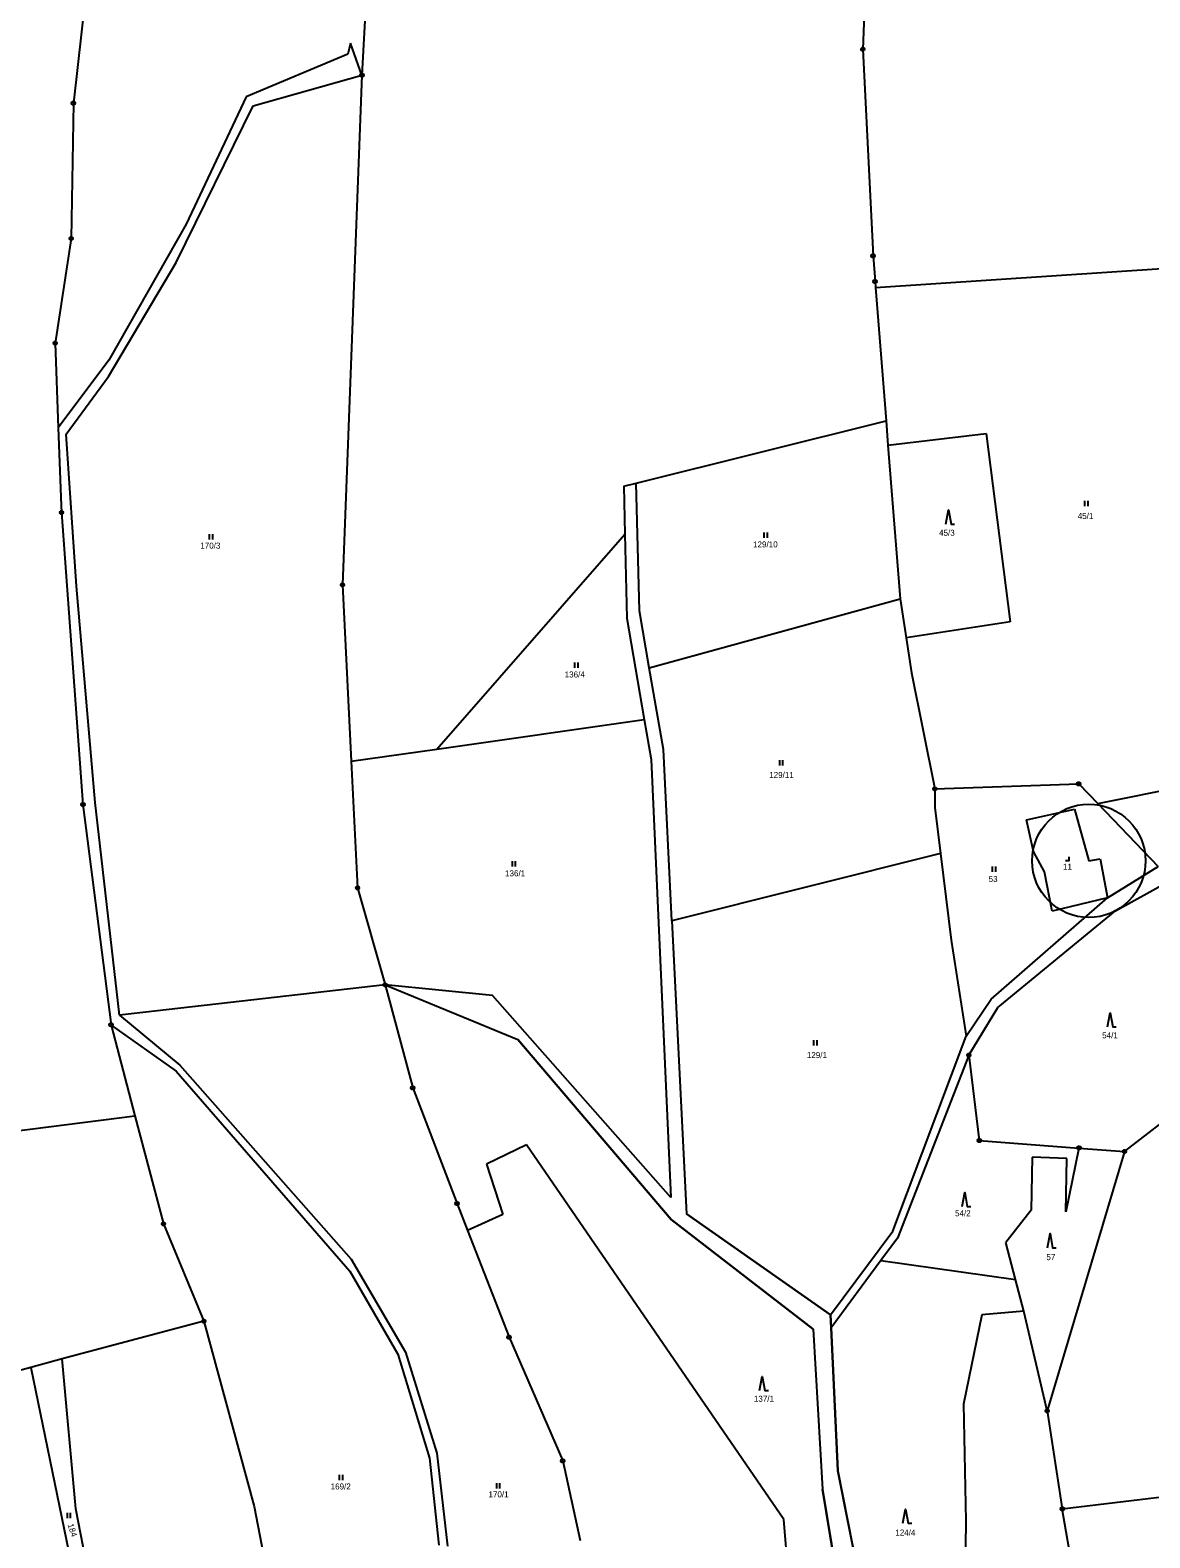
# Model space of a CAD drawing. Extents: x -580551 to -575069, y -1073031 to -1067931.
# Drawn here: x -576954.8 to -576638.6, y -1069440.4 to -1069014.5 of the extents above; entities that cross this region are included whole.
import ezdxf

# ---------------------------------------------------------------- set-up
doc = ezdxf.new("R2010")
doc.units = 0
for name, color, linetype in [('Druh pozemku', 7, 'Continuous'), ('Geodetické body', 7, 'Continuous'), ('Hranice z DKM', 7, 'Continuous'), ('Parcela', 7, 'Continuous'), ('Parcelní číslo', 7, 'Continuous'), ('Parcelní číslo_stavba', 7, 'Continuous'), ('stavební parcely', 7, 'Continuous'), ('Vrstva 6', 7, 'Continuous')]:
    doc.layers.add(name, color=color, linetype=linetype)

msp = doc.modelspace()

# ---------------------------------------------------------------- linework, layer by layer
at = {"layer": 'Druh pozemku'}
for p, q in [((-576657.09, -1069147.52), (-576657.09, -1069149.02)), ((-576656.09, -1069149.02), (-576656.09, -1069147.52)), ((-576904.29, -1069156.88), (-576904.29, -1069158.38)), ((-576903.29, -1069158.38), (-576903.29, -1069156.88)), ((-576747.6, -1069156.45), (-576747.6, -1069157.95)), ((-576746.6, -1069157.95), (-576746.6, -1069156.45)), ((-576801.1, -1069193.21), (-576801.1, -1069194.71)), ((-576800.1, -1069194.71), (-576800.1, -1069193.21)), ((-576743.26, -1069220.78), (-576743.26, -1069222.28)), ((-576742.26, -1069222.28), (-576742.26, -1069220.78)), ((-576818.75, -1069249.32), (-576818.75, -1069250.82)), ((-576817.75, -1069250.82), (-576817.75, -1069249.32)), ((-576683.16, -1069250.75), (-576683.16, -1069252.25)), ((-576682.16, -1069252.25), (-576682.16, -1069250.75)), ((-576733.62, -1069299.84), (-576733.62, -1069301.34)), ((-576732.62, -1069301.34), (-576732.62, -1069299.84)), ((-576867.56, -1069422.63), (-576867.56, -1069424.13)), ((-576866.56, -1069424.13), (-576866.56, -1069422.63)), ((-576823.15, -1069424.94), (-576823.15, -1069426.44)), ((-576822.15, -1069426.44), (-576822.15, -1069424.94)), ((-576944.4, -1069433.34), (-576944.4, -1069434.84)), ((-576943.4, -1069434.84), (-576943.4, -1069433.34))]:
    msp.add_line(p, q, dxfattribs=at)
for points in [[(-576696.28, -1069154.06), (-576695.53, -1069150.06), (-576694.78, -1069154.06), (-576693.78, -1069154.06)], [(-576662.44, -1069249.1), (-576661.44, -1069249.1), (-576661.44, -1069248.1)], [(-576650.61, -1069296.09), (-576649.86, -1069292.09), (-576649.11, -1069296.09), (-576648.11, -1069296.09)], [(-576691.67, -1069346.84), (-576690.92, -1069342.84), (-576690.17, -1069346.84), (-576689.17, -1069346.84)], [(-576667.57, -1069358.5), (-576666.82, -1069354.5), (-576666.07, -1069358.5), (-576665.07, -1069358.5)], [(-576748.82, -1069398.84), (-576748.07, -1069394.84), (-576747.32, -1069398.84), (-576746.32, -1069398.84)], [(-576708.35, -1069436.32), (-576707.6, -1069432.32), (-576706.85, -1069436.32), (-576705.85, -1069436.32)]]:
    msp.add_lwpolyline(points, dxfattribs=at)
at = {"layer": 'Geodetické body'}
for p, q in [((-576719.81, -1069019.97), (-576719.57, -1069019.97)), ((-576861.26, -1069027.25), (-576861.02, -1069027.25)), ((-576942.75, -1069035.14), (-576942.51, -1069035.14)), ((-576943.37, -1069073.41), (-576943.13, -1069073.41)), ((-576716.91, -1069078.31), (-576716.67, -1069078.31)), ((-576716.34, -1069085.54), (-576716.1, -1069085.54)), ((-576947.89, -1069102.98), (-576947.65, -1069102.98)), ((-576946.11, -1069150.82), (-576945.87, -1069150.82)), ((-576866.73, -1069171.24), (-576866.49, -1069171.24)), ((-576699.47, -1069228.86), (-576699.23, -1069228.86)), ((-576658.82, -1069227.41), (-576658.58, -1069227.41)), ((-576940.05, -1069233.25), (-576939.81, -1069233.25)), ((-576862.52, -1069256.8), (-576862.28, -1069256.8)), ((-576854.68, -1069284.2), (-576854.44, -1069284.2)), ((-576932.12, -1069295.57), (-576931.88, -1069295.57)), ((-576689.87, -1069304.12), (-576689.63, -1069304.12)), ((-576846.9, -1069313.32), (-576846.66, -1069313.32)), ((-576686.91, -1069328.19), (-576686.67, -1069328.19)), ((-576658.77, -1069330.31), (-576658.53, -1069330.31)), ((-576645.9, -1069331.31), (-576645.66, -1069331.31)), ((-576834.4, -1069346.03), (-576834.16, -1069346.03)), ((-576917.28, -1069351.77), (-576917.04, -1069351.77)), ((-576905.92, -1069379.22), (-576905.68, -1069379.22)), ((-576819.71, -1069383.71), (-576819.47, -1069383.71)), ((-576667.73, -1069404.55), (-576667.49, -1069404.55)), ((-576804.56, -1069418.68), (-576804.32, -1069418.68)), ((-576663.47, -1069432.24), (-576663.23, -1069432.24))]:
    msp.add_line(p, q, dxfattribs=at)
for points in [[(-576719.54, -1069019.49), (-576719.29, -1069019.67), (-576719.19, -1069019.96), (-576719.29, -1069020.25), (-576719.54, -1069020.43), (-576719.85, -1069020.43), (-576720.1, -1069020.25), (-576720.2, -1069019.96), (-576720.1, -1069019.67), (-576719.85, -1069019.49)], [(-576860.99, -1069026.77), (-576860.74, -1069026.95), (-576860.64, -1069027.24), (-576860.74, -1069027.53), (-576860.99, -1069027.71), (-576861.3, -1069027.71), (-576861.55, -1069027.53), (-576861.65, -1069027.24), (-576861.55, -1069026.95), (-576861.3, -1069026.77)], [(-576942.48, -1069034.66), (-576942.23, -1069034.84), (-576942.13, -1069035.13), (-576942.23, -1069035.42), (-576942.48, -1069035.6), (-576942.79, -1069035.6), (-576943.04, -1069035.42), (-576943.14, -1069035.13), (-576943.04, -1069034.84), (-576942.79, -1069034.66)], [(-576943.1, -1069072.93), (-576942.85, -1069073.11), (-576942.75, -1069073.4), (-576942.85, -1069073.69), (-576943.1, -1069073.87), (-576943.41, -1069073.87), (-576943.66, -1069073.69), (-576943.76, -1069073.4), (-576943.66, -1069073.11), (-576943.41, -1069072.93)], [(-576716.64, -1069077.83), (-576716.39, -1069078.01), (-576716.29, -1069078.3), (-576716.39, -1069078.59), (-576716.64, -1069078.77), (-576716.95, -1069078.77), (-576717.2, -1069078.59), (-576717.3, -1069078.3), (-576717.2, -1069078.01), (-576716.95, -1069077.83)], [(-576716.07, -1069085.06), (-576715.82, -1069085.24), (-576715.72, -1069085.53), (-576715.82, -1069085.82), (-576716.07, -1069086), (-576716.38, -1069086), (-576716.63, -1069085.82), (-576716.73, -1069085.53), (-576716.63, -1069085.24), (-576716.38, -1069085.06)], [(-576947.62, -1069102.5), (-576947.37, -1069102.68), (-576947.27, -1069102.97), (-576947.37, -1069103.26), (-576947.62, -1069103.44), (-576947.93, -1069103.44), (-576948.18, -1069103.26), (-576948.28, -1069102.97), (-576948.18, -1069102.68), (-576947.93, -1069102.5)], [(-576945.84, -1069150.34), (-576945.59, -1069150.52), (-576945.49, -1069150.81), (-576945.59, -1069151.1), (-576945.84, -1069151.28), (-576946.15, -1069151.28), (-576946.4, -1069151.1), (-576946.5, -1069150.81), (-576946.4, -1069150.52), (-576946.15, -1069150.34)], [(-576866.46, -1069170.76), (-576866.21, -1069170.94), (-576866.11, -1069171.23), (-576866.21, -1069171.52), (-576866.46, -1069171.7), (-576866.77, -1069171.7), (-576867.02, -1069171.52), (-576867.12, -1069171.23), (-576867.02, -1069170.94), (-576866.77, -1069170.76)], [(-576699.2, -1069228.38), (-576698.95, -1069228.56), (-576698.85, -1069228.85), (-576698.95, -1069229.14), (-576699.2, -1069229.32), (-576699.51, -1069229.32), (-576699.76, -1069229.14), (-576699.86, -1069228.85), (-576699.76, -1069228.56), (-576699.51, -1069228.38)], [(-576658.55, -1069226.93), (-576658.3, -1069227.11), (-576658.2, -1069227.4), (-576658.3, -1069227.69), (-576658.55, -1069227.87), (-576658.86, -1069227.87), (-576659.11, -1069227.69), (-576659.21, -1069227.4), (-576659.11, -1069227.11), (-576658.86, -1069226.93)], [(-576939.78, -1069232.77), (-576939.53, -1069232.95), (-576939.43, -1069233.24), (-576939.53, -1069233.53), (-576939.78, -1069233.71), (-576940.09, -1069233.71), (-576940.34, -1069233.53), (-576940.44, -1069233.24), (-576940.34, -1069232.95), (-576940.09, -1069232.77)], [(-576862.25, -1069256.32), (-576862, -1069256.5), (-576861.9, -1069256.79), (-576862, -1069257.08), (-576862.25, -1069257.26), (-576862.56, -1069257.26), (-576862.81, -1069257.08), (-576862.91, -1069256.79), (-576862.81, -1069256.5), (-576862.56, -1069256.32)], [(-576854.41, -1069283.72), (-576854.16, -1069283.9), (-576854.06, -1069284.19), (-576854.16, -1069284.48), (-576854.41, -1069284.66), (-576854.72, -1069284.66), (-576854.97, -1069284.48), (-576855.07, -1069284.19), (-576854.97, -1069283.9), (-576854.72, -1069283.72)], [(-576931.85, -1069295.09), (-576931.6, -1069295.27), (-576931.5, -1069295.56), (-576931.6, -1069295.85), (-576931.85, -1069296.03), (-576932.16, -1069296.03), (-576932.41, -1069295.85), (-576932.51, -1069295.56), (-576932.41, -1069295.27), (-576932.16, -1069295.09)], [(-576689.6, -1069303.64), (-576689.35, -1069303.82), (-576689.25, -1069304.11), (-576689.35, -1069304.4), (-576689.6, -1069304.58), (-576689.91, -1069304.58), (-576690.16, -1069304.4), (-576690.26, -1069304.11), (-576690.16, -1069303.82), (-576689.91, -1069303.64)], [(-576846.63, -1069312.84), (-576846.38, -1069313.02), (-576846.28, -1069313.31), (-576846.38, -1069313.6), (-576846.63, -1069313.78), (-576846.94, -1069313.78), (-576847.19, -1069313.6), (-576847.29, -1069313.31), (-576847.19, -1069313.02), (-576846.94, -1069312.84)], [(-576686.64, -1069327.71), (-576686.39, -1069327.89), (-576686.29, -1069328.18), (-576686.39, -1069328.47), (-576686.64, -1069328.65), (-576686.95, -1069328.65), (-576687.2, -1069328.47), (-576687.3, -1069328.18), (-576687.2, -1069327.89), (-576686.95, -1069327.71)], [(-576658.5, -1069329.83), (-576658.25, -1069330.01), (-576658.15, -1069330.3), (-576658.25, -1069330.59), (-576658.5, -1069330.77), (-576658.81, -1069330.77), (-576659.06, -1069330.59), (-576659.16, -1069330.3), (-576659.06, -1069330.01), (-576658.81, -1069329.83)], [(-576645.63, -1069330.83), (-576645.38, -1069331.01), (-576645.28, -1069331.3), (-576645.38, -1069331.59), (-576645.63, -1069331.77), (-576645.94, -1069331.77), (-576646.19, -1069331.59), (-576646.29, -1069331.3), (-576646.19, -1069331.01), (-576645.94, -1069330.83)], [(-576834.13, -1069345.55), (-576833.88, -1069345.73), (-576833.78, -1069346.02), (-576833.88, -1069346.31), (-576834.13, -1069346.49), (-576834.44, -1069346.49), (-576834.69, -1069346.31), (-576834.79, -1069346.02), (-576834.69, -1069345.73), (-576834.44, -1069345.55)], [(-576917.01, -1069351.29), (-576916.76, -1069351.47), (-576916.66, -1069351.76), (-576916.76, -1069352.05), (-576917.01, -1069352.23), (-576917.32, -1069352.23), (-576917.57, -1069352.05), (-576917.67, -1069351.76), (-576917.57, -1069351.47), (-576917.32, -1069351.29)], [(-576905.65, -1069378.74), (-576905.4, -1069378.92), (-576905.3, -1069379.21), (-576905.4, -1069379.5), (-576905.65, -1069379.68), (-576905.96, -1069379.68), (-576906.21, -1069379.5), (-576906.31, -1069379.21), (-576906.21, -1069378.92), (-576905.96, -1069378.74)], [(-576819.44, -1069383.23), (-576819.19, -1069383.41), (-576819.09, -1069383.7), (-576819.19, -1069383.99), (-576819.44, -1069384.17), (-576819.75, -1069384.17), (-576820, -1069383.99), (-576820.1, -1069383.7), (-576820, -1069383.41), (-576819.75, -1069383.23)], [(-576667.46, -1069404.07), (-576667.21, -1069404.25), (-576667.11, -1069404.54), (-576667.21, -1069404.83), (-576667.46, -1069405.01), (-576667.77, -1069405.01), (-576668.02, -1069404.83), (-576668.12, -1069404.54), (-576668.02, -1069404.25), (-576667.77, -1069404.07)], [(-576804.29, -1069418.2), (-576804.04, -1069418.38), (-576803.94, -1069418.67), (-576804.04, -1069418.96), (-576804.29, -1069419.14), (-576804.6, -1069419.14), (-576804.85, -1069418.96), (-576804.95, -1069418.67), (-576804.85, -1069418.38), (-576804.6, -1069418.2)], [(-576663.2, -1069431.76), (-576662.95, -1069431.94), (-576662.85, -1069432.23), (-576662.95, -1069432.52), (-576663.2, -1069432.7), (-576663.51, -1069432.7), (-576663.76, -1069432.52), (-576663.86, -1069432.23), (-576663.76, -1069431.94), (-576663.51, -1069431.76)]]:
    msp.add_lwpolyline(points, close=True, dxfattribs=at)
at = {"layer": 'Hranice z DKM'}
for p, q in [((-576773.93, -1069344.3), (-576824.27, -1069287.21)), ((-576773.8, -1069350.46), (-576817.09, -1069299.67)), ((-576733.7, -1069381.48), (-576773.8, -1069350.46)), ((-576733.7, -1069381.48), (-576731.09, -1069426.71))]:
    msp.add_line(p, q, dxfattribs=at)
for points in [[(-576726.73, -1069421.48), (-576728.63, -1069381.13), (-576728.81, -1069377.4), (-576769.52, -1069348.87)], [(-576711.18, -1069506.06), (-576715.1, -1069480.23), (-576726.73, -1069421.48)], [(-576721.88, -1069508.01), (-576723.55, -1069472.52), (-576731.09, -1069426.71)]]:
    msp.add_lwpolyline(points, dxfattribs=at)
at = {"layer": 'Parcela'}
for p, q in [((-576716.74, -1068937.54), (-576719.69, -1069019.97)), ((-576857.83, -1068965.35), (-576861.14, -1069027.25)), ((-576938.25, -1068996.63), (-576942.63, -1069035.14)), ((-576864.41, -1069018.23), (-576865.12, -1069021.33)), ((-576861.14, -1069027.25), (-576864.41, -1069018.23)), ((-576719.69, -1069019.97), (-576716.79, -1069078.31)), ((-576865.12, -1069021.33), (-576893.85, -1069033.41)), ((-576891.85, -1069035.91), (-576861.14, -1069027.25)), ((-576861.14, -1069027.25), (-576866.61, -1069171.24)), ((-576893.85, -1069033.41), (-576910.76, -1069069.35)), ((-576942.63, -1069035.14), (-576943.25, -1069073.41)), ((-576913.56, -1069080.14), (-576891.85, -1069035.91)), ((-576910.76, -1069069.35), (-576932.63, -1069107.74)), ((-576943.25, -1069073.41), (-576947.77, -1069102.98)), ((-576932.68, -1069112.34), (-576913.56, -1069080.14)), ((-576716.79, -1069078.31), (-576716.22, -1069085.54)), ((-576716.09, -1069087.25), (-576633.74, -1069081.81)), ((-576716.22, -1069085.54), (-576716.09, -1069087.25)), ((-576716.09, -1069087.25), (-576713.13, -1069124.91)), ((-576947.77, -1069102.98), (-576946.88, -1069126.84)), ((-576932.63, -1069107.74), (-576946.88, -1069126.84)), ((-576944.65, -1069128.66), (-576932.68, -1069112.34)), ((-576946.88, -1069126.84), (-576946.07, -1069148.77)), ((-576783.7, -1069142.47), (-576713.13, -1069124.91)), ((-576713.13, -1069124.91), (-576712.59, -1069131.75)), ((-576941.75, -1069171.65), (-576944.65, -1069128.66)), ((-576712.59, -1069131.75), (-576684.82, -1069128.5)), ((-576684.82, -1069128.5), (-576678.08, -1069181.72)), ((-576712.59, -1069131.75), (-576709.18, -1069175.2)), ((-576787.2, -1069143.34), (-576783.7, -1069142.47)), ((-576787.2, -1069143.34), (-576786.89, -1069156.94)), ((-576782.73, -1069178.55), (-576783.7, -1069142.47)), ((-576946.07, -1069148.77), (-576945.99, -1069150.82)), ((-576945.99, -1069150.82), (-576939.93, -1069233.25)), ((-576840.01, -1069217.64), (-576786.89, -1069156.94)), ((-576786.89, -1069156.94), (-576786.34, -1069180.66)), ((-576936.51, -1069232.67), (-576941.75, -1069171.65)), ((-576866.61, -1069171.24), (-576864.16, -1069221.08)), ((-576780.02, -1069194.71), (-576709.18, -1069175.2)), ((-576709.18, -1069175.2), (-576707.47, -1069186.2)), ((-576786.34, -1069180.66), (-576781.39, -1069209.31)), ((-576780.02, -1069194.71), (-576782.73, -1069178.55)), ((-576678.08, -1069181.72), (-576707.47, -1069186.2)), ((-576707.47, -1069186.2), (-576705.92, -1069196.11)), ((-576775.93, -1069217.78), (-576780.02, -1069194.71)), ((-576705.92, -1069196.11), (-576699.35, -1069228.86)), ((-576840.01, -1069217.64), (-576781.39, -1069209.31)), ((-576781.39, -1069209.31), (-576779.48, -1069220.52)), ((-576864.16, -1069221.08), (-576840.01, -1069217.64)), ((-576779.48, -1069220.52), (-576773.93, -1069344.3)), ((-576773.62, -1069266.15), (-576775.93, -1069217.78)), ((-576864.16, -1069221.08), (-576862.4, -1069256.8)), ((-576699.35, -1069228.86), (-576658.7, -1069227.41)), ((-576699.35, -1069228.86), (-576699.34, -1069234.17)), ((-576658.7, -1069227.41), (-576653.31, -1069233.01)), ((-576653.31, -1069233.01), (-576624.42, -1069227.23)), ((-576939.93, -1069233.25), (-576932, -1069295.57)), ((-576929.64, -1069292.78), (-576936.51, -1069232.67)), ((-576653.31, -1069233.01), (-576636.23, -1069250.8)), ((-576699.34, -1069234.17), (-576697.73, -1069247.11)), ((-576673.46, -1069237.6), (-576659.89, -1069234.64)), ((-576671.47, -1069246.57), (-576673.46, -1069237.6)), ((-576659.89, -1069234.64), (-576655.86, -1069249.19)), ((-576697.73, -1069247.11), (-576773.62, -1069266.15)), ((-576697.73, -1069247.11), (-576694.69, -1069271.6)), ((-576668.35, -1069252.27), (-576671.47, -1069246.57)), ((-576655.86, -1069249.19), (-576652.61, -1069248.58)), ((-576652.61, -1069248.58), (-576650.61, -1069259.61)), ((-576648.32, -1069263.29), (-576620.89, -1069248.16)), ((-576666.25, -1069263.38), (-576668.35, -1069252.27)), ((-576650.61, -1069259.61), (-576636.23, -1069250.8)), ((-576862.4, -1069256.8), (-576854.56, -1069284.2)), ((-576683.4, -1069288.27), (-576650.61, -1069259.61)), ((-576681.6, -1069290.65), (-576648.32, -1069263.29)), ((-576650.61, -1069259.61), (-576666.25, -1069263.38)), ((-576773.62, -1069266.15), (-576769.52, -1069348.87)), ((-576694.69, -1069271.6), (-576690.48, -1069298.72)), ((-576854.56, -1069284.2), (-576929.64, -1069292.78)), ((-576854.56, -1069284.2), (-576846.78, -1069313.32)), ((-576854.56, -1069284.2), (-576817.09, -1069299.67)), ((-576824.27, -1069287.21), (-576854.56, -1069284.2)), ((-576773.93, -1069344.3), (-576824.27, -1069287.21)), ((-576690.48, -1069298.72), (-576683.4, -1069288.27)), ((-576929.64, -1069292.78), (-576912.55, -1069306.9)), ((-576689.75, -1069304.12), (-576681.6, -1069290.65)), ((-576932, -1069295.57), (-576925.23, -1069321.19)), ((-576932, -1069295.57), (-576913.62, -1069308.57)), ((-576817.09, -1069299.67), (-576773.8, -1069350.46)), ((-576711.17, -1069353.81), (-576690.48, -1069298.72)), ((-576689.75, -1069304.12), (-576709.92, -1069355.81)), ((-576689.75, -1069304.12), (-576686.79, -1069328.19)), ((-576645.78, -1069331.31), (-576613.08, -1069306.06)), ((-576913.62, -1069308.57), (-576864.55, -1069365.07)), ((-576912.55, -1069306.9), (-576864.21, -1069361.67)), ((-576846.78, -1069313.32), (-576834.28, -1069346.03)), ((-577002.4, -1069331.13), (-576925.23, -1069321.19)), ((-576925.23, -1069321.19), (-576917.16, -1069351.77)), ((-576814.66, -1069329.38), (-576825.92, -1069334.85)), ((-576741.98, -1069435.23), (-576814.66, -1069329.38)), ((-576686.79, -1069328.19), (-576658.65, -1069330.31)), ((-576645.78, -1069331.31), (-576667.61, -1069404.55)), ((-576658.65, -1069330.31), (-576662.38, -1069348.31)), ((-576658.65, -1069330.31), (-576645.78, -1069331.31)), ((-576825.92, -1069334.85), (-576821.32, -1069349.06)), ((-576671.87, -1069332.85), (-576672.13, -1069347.87)), ((-576662.05, -1069333.24), (-576671.87, -1069332.85)), ((-576662.38, -1069348.31), (-576662.05, -1069333.24)), ((-576834.28, -1069346.03), (-576831.34, -1069353.57)), ((-576672.13, -1069347.87), (-576679.28, -1069356.97)), ((-576917.16, -1069351.77), (-576905.8, -1069379.22)), ((-576821.32, -1069349.06), (-576831.34, -1069353.57)), ((-576773.8, -1069350.46), (-576733.7, -1069381.48)), ((-576769.52, -1069348.87), (-576728.81, -1069377.4)), ((-576831.34, -1069353.57), (-576819.59, -1069383.71)), ((-576728.81, -1069377.4), (-576711.17, -1069353.81)), ((-576709.92, -1069355.81), (-576714.59, -1069362.13)), ((-576676.55, -1069367.42), (-576679.28, -1069356.97)), ((-576864.55, -1069365.07), (-576850.96, -1069388.53)), ((-576864.21, -1069361.67), (-576848.82, -1069387.96)), ((-576714.59, -1069362.13), (-576728.63, -1069381.13)), ((-576714.59, -1069362.13), (-576676.55, -1069367.42)), ((-576674.19, -1069376.44), (-576676.55, -1069367.42)), ((-576728.81, -1069377.4), (-576728.63, -1069381.13)), ((-576686.07, -1069377.45), (-576691.21, -1069402.67)), ((-576674.19, -1069376.44), (-576686.07, -1069377.45)), ((-576667.61, -1069404.55), (-576674.19, -1069376.44)), ((-576905.8, -1069379.22), (-576945.77, -1069389.9)), ((-576905.8, -1069379.22), (-576891.6, -1069431.59)), ((-576733.7, -1069381.48), (-576731.09, -1069426.71)), ((-576728.63, -1069381.13), (-576726.73, -1069421.48)), ((-576819.59, -1069383.71), (-576804.44, -1069418.68)), ((-576945.77, -1069389.9), (-576954.64, -1069392.27)), ((-576941.94, -1069432.27), (-576945.77, -1069389.9)), ((-576850.96, -1069388.53), (-576842.09, -1069417.92)), ((-576848.82, -1069387.96), (-576840.03, -1069416.53)), ((-576954.64, -1069392.27), (-576986.06, -1069400.66)), ((-576954.64, -1069392.27), (-576943.89, -1069444.48)), ((-576691.21, -1069402.67), (-576690.56, -1069435.61)), ((-576667.61, -1069404.55), (-576663.35, -1069432.24)), ((-576840.03, -1069416.53), (-576836.99, -1069442.77)), ((-576842.09, -1069417.92), (-576839.38, -1069442.48)), ((-576804.44, -1069418.68), (-576799.5, -1069441.19)), ((-576726.73, -1069421.48), (-576715.1, -1069480.23)), ((-576663.35, -1069432.24), (-576594.7, -1069423.88)), ((-576731.09, -1069426.71), (-576723.55, -1069472.52)), ((-576934.67, -1069468.93), (-576941.94, -1069432.27)), ((-576891.6, -1069431.59), (-576883.83, -1069471.26)), ((-576735.96, -1069508.59), (-576741.98, -1069435.23)), ((-576690.56, -1069435.61), (-576691.07, -1069477.37))]:
    msp.add_line(p, q, dxfattribs=at)
at = {"layer": 'stavební parcely'}
msp.add_circle((-576655.86, -1069249.19), 16.006, dxfattribs=at)
at = {"layer": 'Vrstva 6'}
msp.add_line((-576654.48, -1069483.98), (-576663.35, -1069432.24), dxfattribs=at)

# ---------------------------------------------------------------- texts
at = {"layer": 'Parcelní číslo'}
for s, p in [('45/1', (-576658.995, -1069152.63)), ('45/3', (-576698.159, -1069157.37)), ('170/3', (-576906.787, -1069161)), ('129/10', (-576750.682, -1069160.65)), ('136/4', (-576803.889, -1069197.39)), ('129/11', (-576746.131, -1069225.78)), ('136/1', (-576820.722, -1069253.57)), ('53', (-576684.154, -1069255.16)), ('54/1', (-576652.085, -1069299.33)), ('129/1', (-576735.5, -1069304.91)), ('54/2', (-576693.647, -1069349.59)), ('57', (-576667.842, -1069361.98)), ('137/1', (-576750.456, -1069402)), ('169/2', (-576869.977, -1069426.76)), ('170/1', (-576825.403, -1069429)), ('124/4', (-576710.507, -1069439.78))]:
    msp.add_text(s, height=1.7, dxfattribs=at).set_placement(p)
msp.add_text('184', height=1.7, rotation=287.96859, dxfattribs=at).set_placement((-576944.284, -1069436.71))
at = {"layer": 'Parcelní číslo_stavba'}
msp.add_text('11', height=1.7, dxfattribs=at).set_placement((-576663.152, -1069251.71))

doc.saveas('drawing.dxf')
